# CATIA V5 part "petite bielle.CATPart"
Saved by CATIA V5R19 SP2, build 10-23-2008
Part number: petite bielle
Publications: "entraxe", "diamètre petite bielle", "epaisseur", "diamètre pivot"
Bounding box of the stored display mesh (mm): x -5 to 5, y -10 to 50, z -10 to 10
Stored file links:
  C:\Users\pierre\Documents\IFMA\IAO\petite bielle.CATPart
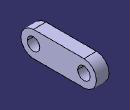
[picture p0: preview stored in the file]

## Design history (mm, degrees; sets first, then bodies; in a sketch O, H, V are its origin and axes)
Parameters
  entraxe = 40 mm
  `diamètre petite bielle` = 20 mm
  epaisseur = 5 mm
  `diamètre pivot` = 10 mm
Body1 (main body)
  Point1: (0, 0, 0)
  Point2: (0, 40 {= entraxe}, 0)
  Line1: type PtPt, FirstPoint Point1, SecondPoint Point2
  Plane1: type OffsetPt, RefPlane yz-plane, RefPoint Point2
  Sketch1 on Plane1, origin (0, 0, 0), H (0, 1, 0), V (0, 0, 1)
    line L1 (0, 10) -> (40, 10)
    arc A1 centre (40, 0) radius 10 from (40, 10) to (40, -10) cw
    point P3 (40, 0)
    arc A2 centre (0, 0) radius 10 from (0, -10) to (0, 10) cw
    point P6 (0, 0)
    reference projected point E1 (40, 0) from Point2
    reference projected point E2 (0, 0) from Point1
    line L2 (40, -10) -> (0, -10)
    radius A1 = 10 {= `diamètre petite bielle` /2}
    radius A2 = 10 {= `diamètre petite bielle` /2}
    tangency: A1 L1, L1 A2, L2 A2, A1 L2
    coincidence: P3 E1, E2 P6
  Pad1: profile Sketch1, direction (1, 0, 0), length 5 {= epaisseur}, mirrored extent
  Sketch2 on Plane1, origin (0, 0, 0), H (0, 1, 0), V (0, 0, 1)
    circle A1 centre (40, 0) radius 5
    point P1 (40, 0)
    circle A2 centre (0, 0) radius 5
    point P2 (0, 0)
    reference projected point E1 (40, 0) from Point2
    reference projected point E2 (0, 0) from Point1
    radius A1 = 5 {= `diamètre pivot` /2}
    radius A2 = 5 {= `diamètre pivot` /2}
    coincidence: P1 E1, P2 E2
  Pocket1: profile Sketch2, direction (-1, 0, 0), through (limit type 6), opposite side length 5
